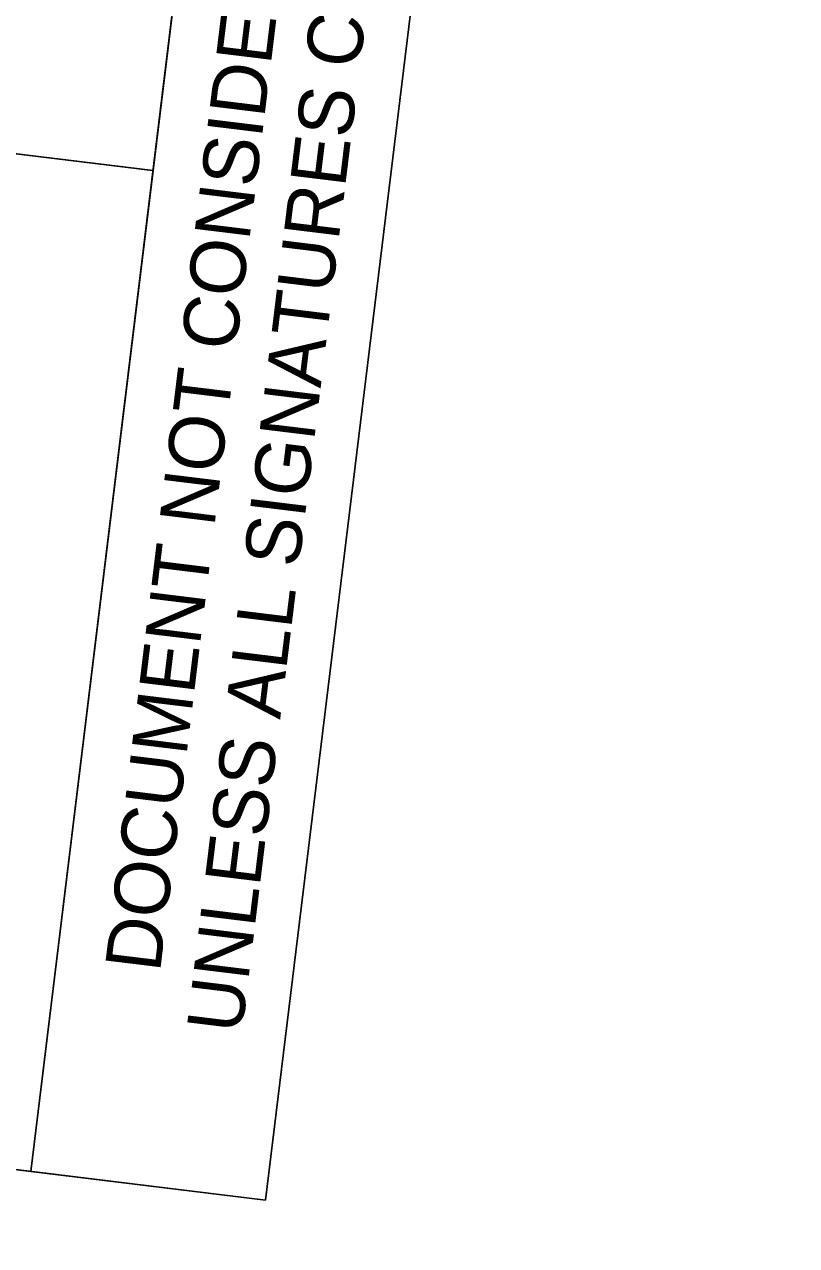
# Model space of a CAD drawing. Extents: x 480344 to 482186, y 488805 to 491553.
# Drawn here: x 480964.2 to 481040.8, y 490365.2 to 490486.4 of the extents above; entities that cross this region are included whole.
import ezdxf

# ---------------------------------------------------------------- set-up
doc = ezdxf.new("R2010")
doc.units = 0
for name, color, linetype in [('Sheet Layout Plan Border', 7, 'Continuous'), ('Sheet Plan CELL', 7, 'Continuous'), ('Sheet Sticker Exception Certification CELL', 7, 'Continuous')]:
    doc.layers.add(name, color=color, linetype=linetype)

msp = doc.modelspace()

# ---------------------------------------------------------------- linework, layer by layer
at = {"layer": 'Sheet Layout Plan Border'}
msp.add_lwpolyline([(481703.23, 488995.25), (481861.69, 490292.69), (481782.27, 490302.39), (481802.94, 490471.69), (481574.79, 490460.72), (481089.79, 490519.96), (481007.71, 490529.98), (480988.13, 490369.7), (480815.85, 490390.73), (480660.97, 489122.55)], close=True, dxfattribs=at)
at = {"layer": 'Sheet Plan CELL'}
for p, q in [((480964.81, 490372.55), (480989.07, 490571.11)), ((480865.28, 490485.49), (480976.91, 490471.86)), ((480815.85, 490390.73), (480964.81, 490372.55))]:
    msp.add_line(p, q, dxfattribs=at)
for points in [[(480865.28, 490485.49), (480877.39, 490584.74), (480989.07, 490571.11), (480976.96, 490471.85)], [(480853.15, 490386.17), (480865.28, 490485.49), (480976.96, 490471.85), (480964.81, 490372.55)]]:
    msp.add_lwpolyline(points, close=True, dxfattribs=at)
at = {"layer": 'Sheet Sticker Exception Certification CELL'}
for p, q in [((480964.81, 490372.55), (480989.06, 490571.11)), ((480964.81, 490372.55), (480989.06, 490571.11)), ((480964.81, 490372.55), (480989.06, 490571.11)), ((481012.39, 490568.26), (480988.13, 490369.7)), ((481012.39, 490568.26), (480988.13, 490369.7)), ((481012.39, 490568.26), (480988.13, 490369.7)), ((480988.13, 490369.7), (480964.81, 490372.55)), ((480988.13, 490369.7), (480964.81, 490372.55)), ((480988.13, 490369.7), (480964.81, 490372.55))]:
    msp.add_line(p, q, dxfattribs=at)

# ---------------------------------------------------------------- texts
for s, p in [('UNLESS ALL SIGNATURES COMPLETED', (480985.75, 490386.11)), ('UNLESS ALL SIGNATURES COMPLETED', (480985.75, 490386.11)), ('UNLESS ALL SIGNATURES COMPLETED', (480985.75, 490386.11)), ('DOCUMENT NOT CONSIDERED FINAL', (480977.63, 490392.21)), ('DOCUMENT NOT CONSIDERED FINAL', (480977.63, 490392.21)), ('DOCUMENT NOT CONSIDERED FINAL', (480977.63, 490392.21))]:
    msp.add_text(s, height=5.5, rotation=83.0365, dxfattribs=at).set_placement(p)

doc.saveas('drawing.dxf')
